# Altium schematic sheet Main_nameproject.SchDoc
size A4
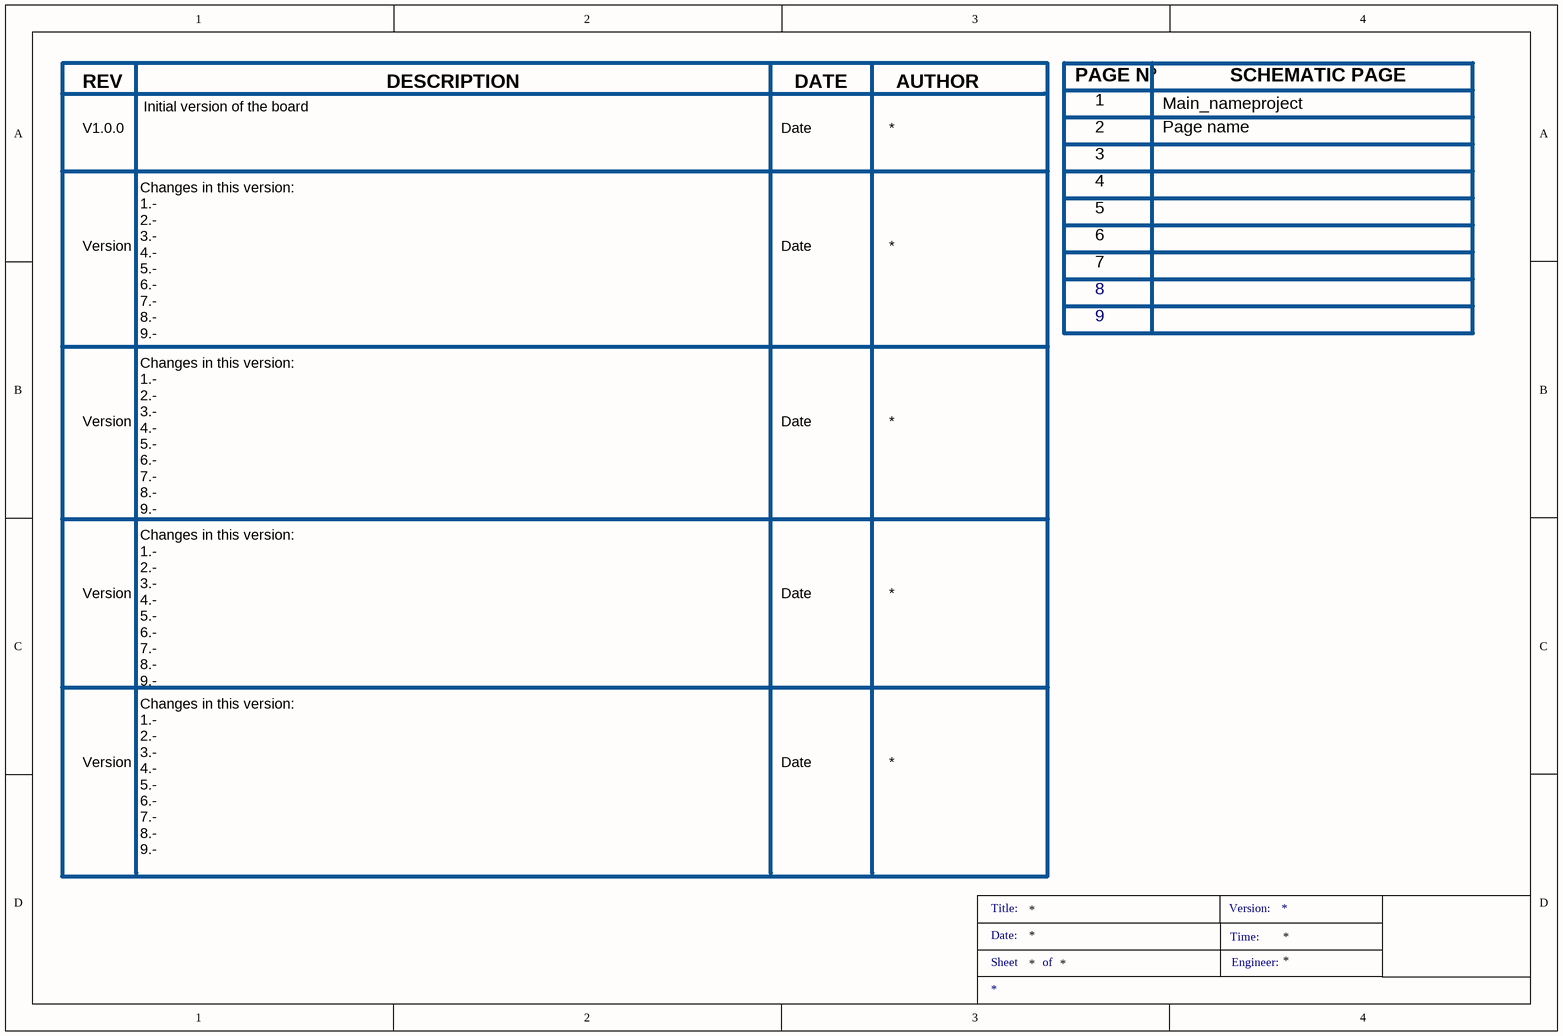
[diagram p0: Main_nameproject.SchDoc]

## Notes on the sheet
- REV
- DESCRIPTION
- DATE
- AUTHOR
- PAGE Nº
- 1
- Main_nameproject
- SCHEMATIC PAGE
- V1.0.0
- Initial version of the board
- Date
- 2
- 3
- Page name
- 4
- 5
- 6
- Version
- 7
- 8
- Changes in this version:
  1.-
  2.-
  3.-
  4.-
  5.-
  6.-
  7.-
  8.-
  9.-
- 9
